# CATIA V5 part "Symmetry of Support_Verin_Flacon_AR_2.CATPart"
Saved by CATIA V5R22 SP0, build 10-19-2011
Part number: Symmetry of Support_Verin_Flacon_AR_2
Bounding box of the stored display mesh (mm): x 0 to 9, y -28.5 to 28.5, z -20 to 18.5
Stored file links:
  D:\PER\CAO_PER_MODIF_2025\CAO_PER_pick&place_2024P\Sous_Ensemble_Flacon\Symmetry of Support_Verin_Flacon_AR_2.CATPart
  D:\PER\CAO_PER_MODIF_2025\CAO_PER_pick&place_2024P\Sous_Ensemble_Flacon\Support_Verin_Flacon_AR_2.CATPart
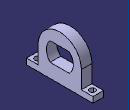
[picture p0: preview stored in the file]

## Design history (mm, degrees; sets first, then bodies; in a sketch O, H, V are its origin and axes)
Body1 (main body)
  Body2 "Corps du corps principal d'origine"
    Solid1: linked copy from another document
  Assemble1: tool Body2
